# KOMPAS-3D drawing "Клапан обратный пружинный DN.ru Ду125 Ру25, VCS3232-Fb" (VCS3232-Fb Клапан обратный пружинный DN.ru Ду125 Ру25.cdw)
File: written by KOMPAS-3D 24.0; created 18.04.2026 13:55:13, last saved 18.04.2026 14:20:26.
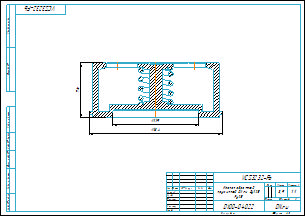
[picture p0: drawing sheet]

Document properties: c3d_UniqueCompID: 071bd168-1a06-425c-849c-e99e84a96128; Наименование: Деталь; Автор: 712; Класс точности: c; Знак неуказанной шероховатости: Шероховатость не задана; Рассекать на разрезах: Да; c3d_UniqueCompID: 071bd168-1a06-425c-849c-e99e84a96128; Наименование: Деталь; Автор: 712; Класс точности: c; Знак неуказанной шероховатости: Шероховатость не задана; Рассекать на разрезах: Да; c3d_UniqueCompID: 071bd168-1a06-425c-849c-e99e84a96128; Наименование: Деталь; Автор: 712; Класс точности: c; Знак неуказанной шероховатости: Шероховатость не задана; Рассекать на разрезах: Да; c3d_UniqueCompID: 071bd168-1a06-425c-849c-e99e84a96128; Наименование: Деталь; Автор: 712; Класс точности: c; Знак неуказанной шероховатости: Шероховатость не задана; Рассекать на разрезах: Да; c3d_UniqueCompID: 071bd168-1a06-425c-849c-e99e84a96128; Наименование: Деталь; Автор: 712; Класс точности: c; Знак неуказанной шероховатости: Шероховатость не задана; Рассекать на разрезах: Да; c3d_UniqueCompID: 071bd168-1a06-425c-849c-e99e84a96128; Наименование: Деталь; Автор: 712; Класс точности: c; Знак неуказанной шероховатости: Шероховатость не задана; Рассекать на разрезах: Да; c3d_UniqueCompID: 071bd168-1a06-425c-849c-e99e84a96128; Наименование: Деталь; Автор: 712; Класс точности: c; Знак неуказанной шероховатости: Шероховатость не задана; Рассекать на разрезах: Да; c3d_UniqueCompID: 071bd168-1a06-425c-849c-e99e84a96128; Наименование: Деталь; Автор: 712; Класс точности: c; Знак неуказанной шероховатости: Шероховатость не задана; Рассекать на разрезах: Да; c3d_UniqueCompID: 071bd168-1a06-425c-849c-e99e84a96128; Наименование: Деталь; Автор: 712; Класс точности: c; Знак неуказанной шероховатости: Шероховатость не задана; Рассекать на разрезах: Да; c3d_UniqueCompID: 071bd168-1a06-425c-849c-e99e84a96128; Наименование: Деталь; Автор: 712; Класс точности: c; Знак неуказанной шероховатости: Шероховатость не задана; Рассекать на разрезах: Да; Автор: 712; Форматы листов документа: A3; Полное имя файла: VCS3232-Fb Клапан обратный пружинный DN.ru Ду125 Ру25.m3d; Масса: 3.9; Наименование: Клапан обратный пружинный DN.ru Ду125 Ру25; Количество листов документа: 1; Примечание: D100-04022

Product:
- Component: Пружина 1086-1017 ГОСТ 18793-80  | qty 1  | additional columns: 3953604318-4147491677-0; Деталь; Пользователь Windows; c; Шероховатость не задана; Да; Сталь 10  ГОСТ 1050-88; source file: Деталь_1.m3d
- Body: Тело 1  | qty 1
    Масса: 4.808113
- Part/product: Клапан обратный пружинный DN.ru Ду125 Ру25  | designation VCS3232-Fb
    Масса: 3.9
    Раздел спецификации: Прочие изделия
    Примечание: D100-04022
    additional columns: 071bd168-1a06-425c-849c-e99e84a96128; Деталь; 712; c; Шероховатость не задана; Да

Views: Вид 1, Местный разрез 1, Спереди
Referenced files in C:\Users\712\Desktop\Новая папка (4)\: VCS3232-Fb Клапан обратный пружинный DN.ru Ду15 Ру40.m3d, VCS3232-Fb Клапан обратный пружинный DN.ru Ду125 Ру25.m3d, VCS3232-Fb Клапан обратный пружинный DN.ru Ду15 Ру40.cdw
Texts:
  VCS3232-Fb
  Клапан обратный
  пружинный DN.ru Ду125
  Ру25
  Клапан обратный пружинный DN.ru Ду125 Ру25
  VCS3232-Fb Клапан обратный пружинный DN.ru Ду125 Ру25
Dimensions and other numbers on the sheet: 0; 3; 2; 4; 184; 119; 76; 1:1; 1; 3,9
